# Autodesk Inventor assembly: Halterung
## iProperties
Shininess: 64.0
Length Units: 11269
Angle Units: 11279
Time Units: 11290
Mass Units: 11283
Length Display Precision: 3
Angle Display Precision: 2
Compacted: True
Created: 2004-05
Part Number: Halterung
Document SubType Name: Assembly
Designer: mp
Density: 0.0
Volumn: 0.0
Area: 0.0
PropertySet Name: Model Information
Control State: 0
Master: False
Checked Out: False
Author: mp
